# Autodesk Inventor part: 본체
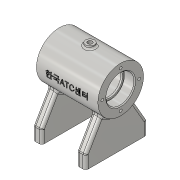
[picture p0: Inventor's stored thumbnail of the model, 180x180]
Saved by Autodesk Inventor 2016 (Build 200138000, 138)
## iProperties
Created: 2018-05
Part Number: 본체
Material: 알루미늄 6061
Document SubType Name: Modeling
Designer: Administrator
Density: 2.7 g/cm^3
Appearance: 알루미늄 - 평지
Mass: 317.68 g
Surface Area: 375.828 cm^2
Volume: 117.659 cm^3
Author: Administrator
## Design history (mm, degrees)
sketch "스케치1"
  geometry: L1 (-35, 0)-(35, 0); L2 (35, 26)-(-35, 26); L3 (-35, 26)-(-35, 16); L4 (-35, 16)-(-23, 16); L5 (-23, 16)-(-23, 14); L6 (-23, 14)-(-21, 14); L7 (-21, 14)-(-21, 21); L8 (-21, 21)-(21, 21); L9 (21, 21)-(21, 14); L10 (21, 14)-(23, 14); L11 (23, 14)-(23, 16); L12 (35, 26)-(35, 16); L13 (35, 16)-(23, 16); 1 further point
  constraints: 26 end point, 9 perpendicular, 3 point on line, 2 collinear, 2 vertical alignment, 1 horizontal, 1 midpoint, 1 parallel, 1 vertical
  dimensions: "d0" = 70 distance of L1.start L1.end; "d1" = 35 distance of L1.start point (0, 0); "d2" = 12 distance of L12.end L11.end; "d3" = 42 distance of L7.end L8.end; "d4" = 32 diameter of L13 L1; "d5" = 28 diameter of L10 L1; "d6" = 42 diameter of L8 L1; "d7" = 52 diameter of L2 L1
revolve "회전1" sketch "스케치1" stored, may be unused: angle "d8" = 90 deg
node "작업 평면2"
sketch "스케치3"
  geometry: C1 r 5 at (0, 0); 1 further point
  constraints: 1 centre point, 1 coincident
  dimensions: "d10" = 10 diameter of C1
extrude "돌출1" join sketch "스케치3" stored distance "d11" = 10; taper "d12" = 0 deg
node "작업 평면3"
sketch "스케치4"
  geometry: L1 (-19.386, 17.325)-(-50, 35); L2 (-50, 35)-(-65, 35); L3 (-65, 35)-(-65, -35); L4 (-65, -35)-(-50, -35); L5 (-50, -35)-(-19.386, -17.325); A1 r 26 centre (0, 0) between (-19.386, 17.325) and (-19.386, -17.325) reference; 1 further point
  constraints: 10 end point, 2 equal length, 2 perpendicular, 2 point on circle, 1 horizontal, 1 horizontal alignment, 1 midpoint
  dimensions: "d14" = 70 distance of L2.end L3.end; "d15" = 30 deg angle of L5 L4; "d16" = 15 distance of L3.end L4.end; "d17" = 65 distance from line of L3 A1.centre
extrude "돌출2" join sketch "스케치4" distance "d18" = 10; taper "d19" = 0 deg
sketch "스케치6"
  geometry: L1 (0, 0)-(26, 0); L2 (0, 0)-(-27.251, -9.919)
  constraints: 4 end point, 1 horizontal, 1 horizontal alignment, 1 other
  dimensions: "d20" = 29 distance of L1.start L2.end; "d21" = 20 deg angle of L1 L2
node "작업 평면4"
sketch "스케치7"
  geometry: C1 r 6 at (0, 0); 1 further point
  constraints: 1 centre point, 1 coincident
  dimensions: "d22" = 12 diameter of C1
extrude "돌출3" join sketch "스케치7" stored distance "d23" = 10; taper "d24" = 0 deg
hole "구멍1" diameter "d27" = 5.188; stored, may be unused: countersink angle "d31" = 90 deg, drill point angle "d33" = 118 deg; dims "d25" = 10, "d26" = 10, "d28" = 12, "d29" = 4, "d30" = 2, "d32" = 21.75
hole "구멍2" diameter "d36" = 5.188; stored, may be unused: countersink angle "d40" = 90 deg, drill point angle "d42" = 118 deg; dims "d34" = 10, "d35" = 10, "d37" = 12, "d38" = 4, "d39" = 2, "d41" = 21.75
sketch "스케치9"
  geometry: L1 (0, 70)-(10, 70) reference; L2 (0, 0)-(10, 0) reference; 4 further points
  constraints: 2 midpoint, 2 vertical alignment
  dimensions: "d43" = 15 distance of point (5, 70) point (5, 55); "d44" = 15 distance from line of L2 point (5, 15)
hole "구멍3" sketch "스케치9" at (5, 55), (5, 15) diameter "d45" = 4.134; stored, may be unused: countersink angle "d49" = 90 deg, drill point angle "d51" = 118 deg; dims "d46" = 8, "d47" = 4, "d48" = 2, "d50" = 10
sketch "스케치10" dims "d52" = 42
  geometry: C1 r 26 at (0, 0) reference; 2 further points
  constraints: 2 vertical alignment, 1 coincident, 2 other
hole "구멍4" sketch "스케치10" at (0, 21) diameter "d53" = 3.242; stored, may be unused: countersink angle "d57" = 90 deg, drill point angle "d59" = 118 deg; dims "d54" = 8, "d55" = 4, "d56" = 2, "d58" = 10
node "작업 평면5"
sketch "스케치11"
  geometry: L1 (-35, 26)-(35, 26) reference; L2 (-35, -26)-(-35, 26) reference; 1 further point
  constraints: 1 other
  dimensions: "d63" = 26 distance from line of point (0, 0) L1; "d64" = 35 distance from line of point (0, 0) L2
feature "엠보싱1" sketch "스케치11" dims "d0" = 70, "d1" = 35, "d2" = 12, "d3" = 42, "d4" = 32, "d5" = 28, "d6" = 42, "d7" = 52, "d65" = 0.5, "d66" = 0
fillet "모깎기1" dims "d67" = 2
fillet "모깎기2" dims "d68" = 3
fillet "모깎기3" dims "d69" = 3
fillet "모깎기4" dims "d70" = 3
fillet "모깎기5" dims "d71" = 0.3
chamfer "모따기1" distance "d72" = 1; stored, may be unused: second distance "d73" = 2, angle "d74" = 45 deg
fillet "모깎기6" dims "d75" = 3
node "솔리드1"
mirror "대칭1"
mirror "대칭2"
pattern_circular "원형 패턴1" dims angle "d61" = 360 deg
mirror "대칭3"
other parameters: "d9" = 29
